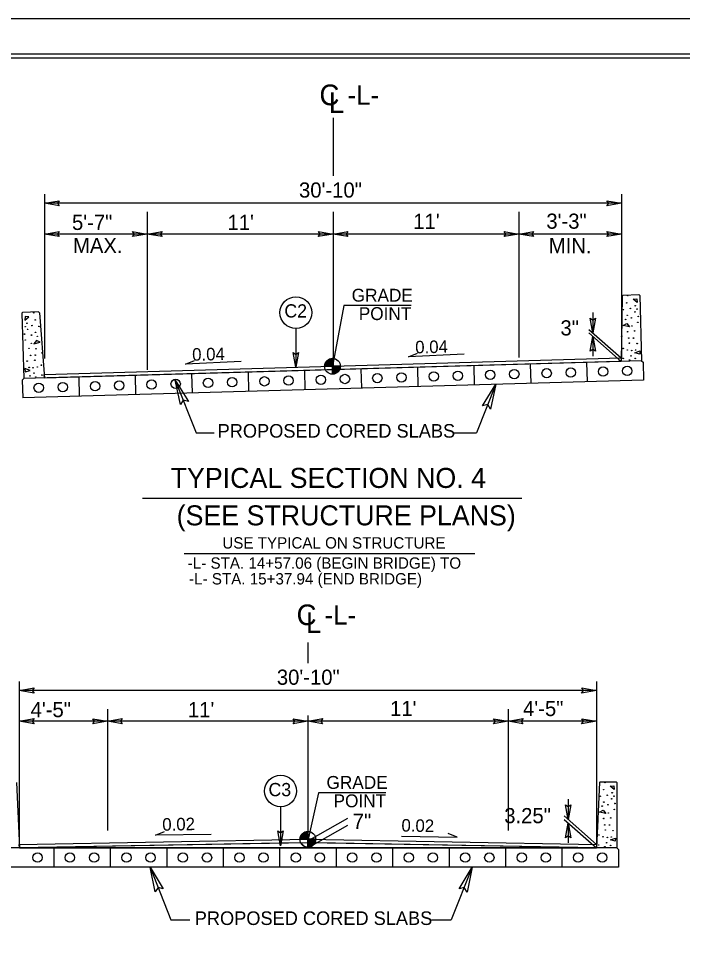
# Model space of a CAD drawing. Extents: x 573687 to 575553, y -54556 to -52223.
# Drawn here: x 574539 to 574960, y -52818 to -52223 of the extents above; entities that cross this region are included whole.
import ezdxf

# ---------------------------------------------------------------- set-up
doc = ezdxf.new("R2010")
doc.units = 0
for name, color, linetype in [('Old_Level_1', 7, 'Continuous'), ('Old_Level_11', 7, 'Continuous'), ('Old_Level_35', 7, 'Continuous'), ('Prop Dimension', 7, 'Continuous'), ('Prop Dimension Text', 7, 'Continuous'), ('Sheet Cutting Line CELL', 7, 'Continuous'), ('Sheet Plot Border Inside CELL', 7, 'Continuous'), ('Sheet Plot Border Outside CELL', 7, 'Continuous'), ('Sheet Typical CELL', 7, 'Continuous'), ('Typical Bridge Rail CELL', 7, 'Continuous'), ('Typical Terminator CELL', 7, 'Continuous'), ('Typical Text Centerline CELL', 7, 'Continuous'), ('Typical Text Grade Point CELL', 7, 'Continuous'), ('Typical Text Label CELL', 7, 'Continuous')]:
    doc.layers.add(name, color=color, linetype=linetype)

msp = doc.modelspace()

# ---------------------------------------------------------------- linework, layer by layer
at = {"layer": 'Old_Level_1'}
for p, q in [((574929.04, -52400.96), (574931.37, -52400.62)), ((574931.37, -52400.62), (574931.59, -52402.96)), ((574931.59, -52402.96), (574929.04, -52400.96)), ((574542.83, -52411.79), (574542.75, -52414.15)), ((574542.75, -52414.15), (574545.18, -52412)), ((574545.18, -52412), (574542.83, -52411.79)), ((574922.69, -52417.62), (574925.06, -52416.28)), ((574926.88, -52418.34), (574922.69, -52417.62)), ((574925.06, -52416.28), (574926.88, -52418.34)), ((574550.03, -52427.06), (574548.34, -52429.23)), ((574548.34, -52429.23), (574552.47, -52428.27)), ((574552.47, -52428.27), (574550.03, -52427.06)), ((574786.36, -52437.5), (574792.21, -52435.19)), ((574821.79, -52435.83), (574786.36, -52437.5)), ((574930.19, -52435.06), (574933.43, -52433.75)), ((574933.25, -52435.77), (574930.19, -52435.06)), ((574933.43, -52433.75), (574933.25, -52435.77)), ((574934.5, -52440.05), (574541.98, -52451.34)), ((574644.68, -52442.15), (574650.53, -52439.84)), ((574680.12, -52440.48), (574644.68, -52442.15)), ((574863.72, -52442.21), (574864.07, -52454.21)), ((574899.57, -52441.18), (574899.92, -52453.17)), ((574935.45, -52440.95), (574935.78, -52452.27)), ((574542.68, -52444.99), (574542.98, -52446.99)), ((574545.99, -52446.11), (574542.68, -52444.99)), ((574542.98, -52446.99), (574545.99, -52446.11)), ((574648.61, -52448.4), (574648.96, -52460.39)), ((574684.46, -52447.37), (574684.81, -52459.36)), ((574720.31, -52446.33), (574720.66, -52458.33)), ((574756.17, -52445.3), (574756.51, -52457.3)), ((574792.02, -52444.27), (574792.36, -52456.27)), ((574827.87, -52443.24), (574828.22, -52455.24)), ((574541.08, -52452.3), (574541.4, -52463.61)), ((574935.78, -52452.27), (574541.4, -52463.61)), ((574576.91, -52450.46), (574577.25, -52462.46)), ((574612.76, -52449.43), (574613.1, -52461.42)), ((574638.24, -52452.27), (574651.53, -52485.76)), ((574841.81, -52454.97), (574829.59, -52485.76)), ((574651.53, -52485.76), (574663, -52485.76)), ((574814.88, -52485.76), (574829.59, -52485.76)), ((574914.5, -52710.39), (574916.84, -52710.11)), ((574917, -52712.46), (574914.5, -52710.39)), ((574916.84, -52710.11), (574917, -52712.46)), ((574907.68, -52726.85), (574910.09, -52725.58)), ((574911.84, -52727.7), (574907.68, -52726.85)), ((574910.09, -52725.58), (574911.84, -52727.7)), ((574625.63, -52741.53), (574631.48, -52739.22)), ((574817.37, -52742.66), (574811.53, -52740.34)), ((574661.1, -52740.94), (574625.63, -52741.53)), ((574781.9, -52742.06), (574817.37, -52742.66)), ((574914.68, -52744.5), (574917.95, -52743.29)), ((574917.71, -52745.29), (574914.68, -52744.5)), ((574917.95, -52743.29), (574917.71, -52745.29)), ((574918.83, -52749.61), (574526.16, -52749.61)), ((574561.09, -52749.74), (574561.09, -52761.74)), ((574596.96, -52749.74), (574596.96, -52761.74)), ((574632.83, -52749.74), (574632.83, -52761.74)), ((574668.7, -52749.74), (574668.7, -52761.74)), ((574704.56, -52749.74), (574704.56, -52761.74)), ((574740.43, -52749.74), (574740.43, -52761.74)), ((574776.3, -52749.74), (574776.3, -52761.74)), ((574812.16, -52749.74), (574812.16, -52761.74)), ((574848.03, -52749.74), (574848.03, -52761.74)), ((574883.9, -52749.74), (574883.9, -52761.74)), ((574919.76, -52750.54), (574919.76, -52761.86)), ((574919.76, -52761.86), (574525.23, -52761.86)), ((574622.23, -52761.86), (574635.52, -52795.36)), ((574826.87, -52761.86), (574813.58, -52795.36)), ((574635.52, -52795.36), (574647.44, -52795.36)), ((574801.05, -52795.36), (574813.58, -52795.36))]:
    msp.add_line(p, q, dxfattribs=at)
for centre, radius in [((574925.7, -52398.66), 0.174), ((574925.01, -52403.21), 0.174), ((574927.34, -52406.73), 0.174), ((574930.42, -52405.06), 0.174), ((574548.38, -52409.51), 0.174), ((574922.93, -52407.5), 0.174), ((574925.32, -52411.14), 0.174), ((574927.97, -52412.76), 0.174), ((574930.24, -52408.93), 0.174), ((574931.62, -52407.18), 0.174), ((574932.36, -52411.84), 0.174), ((574542.96, -52418.35), 0.174), ((574544.04, -52416.18), 0.174), ((574547.21, -52417.66), 0.174), ((574549.33, -52414.02), 0.174), ((574551.66, -52418.18), 0.174), ((574924.32, -52413.72), 0.174), ((574928.33, -52417.95), 0.174), ((574932.09, -52415.6), 0.174), ((574542.49, -52423.05), 0.174), ((574544.44, -52420.02), 0.174), ((574546.93, -52423.72), 0.174), ((574549.48, -52421.95), 0.174), ((574550.63, -52424.47), 0.174), ((574921.85, -52424.43), 0.174), ((574925.57, -52421.58), 0.174), ((574930, -52421.03), 0.174), ((574542.97, -52426.79), 0.174), ((574546.86, -52428.93), 0.174), ((574926.32, -52425.62), 0.174), ((574926.75, -52428.82), 0.174), ((574929.31, -52425.58), 0.174), ((574931.64, -52429.1), 0.174), ((574545.38, -52432.09), 0.174), ((574546.33, -52436.6), 0.174), ((574549.31, -52436.46), 0.174), ((574549.83, -52432.39), 0.174), ((574553.7, -52435.01), 0.174), ((574922.77, -52432.16), 0.174), ((574925.42, -52433.16), 0.174), ((574928.19, -52433.52), 0.174), ((574930.63, -52433.14), 0.174), ((574544.2, -52440.24), 0.174), ((574549.06, -52439.68), 0.174), ((574553.23, -52442.79), 0.174), ((574922.81, -52438.51), 0.174), ((574926.77, -52439.51), 0.174), ((574927.77, -52436.92), 0.174), ((574930.42, -52438.54), 0.174), ((574545.44, -52444.22), 0.174), ((574547.89, -52444.46), 0.174), ((574548.51, -52447.83), 0.174), ((574550.64, -52443.94), 0.174), ((574766.61, -52451.01), 2.98), ((574781.92, -52450.57), 2.98), ((574802.47, -52449.97), 2.98), ((574817.77, -52449.53), 2.98), ((574838.32, -52448.94), 2.98), ((574853.62, -52448.5), 2.98), ((574874.17, -52447.91), 2.98), ((574889.47, -52447.47), 2.98), ((574910.02, -52446.88), 2.98), ((574925.32, -52446.44), 2.98), ((574545.96, -52449.6), 0.174), ((574551.5, -52457.19), 2.98), ((574549.66, -52450.35), 0.174), ((574553.55, -52449.13), 0.174), ((574566.8, -52456.75), 2.98), ((574587.35, -52456.16), 2.98), ((574602.66, -52455.72), 2.98), ((574623.21, -52455.13), 2.98), ((574638.51, -52454.69), 2.98), ((574659.06, -52454.1), 2.98), ((574674.36, -52453.66), 2.98), ((574694.91, -52453.07), 2.98), ((574710.21, -52452.63), 2.98), ((574730.76, -52452.04), 2.98), ((574746.06, -52451.6), 2.98), ((574911.23, -52707.99), 0.174), ((574908.21, -52716.74), 0.174), ((574910.41, -52712.52), 0.174), ((574912.64, -52716.1), 0.174), ((574915.77, -52714.52), 0.174), ((574916.91, -52716.67), 0.174), ((574910.49, -52720.45), 0.174), ((574913.09, -52722.14), 0.174), ((574915.48, -52718.38), 0.174), ((574917.51, -52721.35), 0.174), ((574909.42, -52723.01), 0.174), ((574913.31, -52727.35), 0.174), ((574917.14, -52725.1), 0.174), ((574906.64, -52733.63), 0.174), ((574910.44, -52730.89), 0.174), ((574914.88, -52730.47), 0.174), ((574911.08, -52734.95), 0.174), ((574911.42, -52738.16), 0.174), ((574914.07, -52735), 0.174), ((574916.29, -52738.58), 0.174), ((574907.34, -52741.39), 0.174), ((574909.96, -52742.46), 0.174), ((574912.21, -52746.29), 0.174), ((574912.72, -52742.9), 0.174), ((574915.17, -52742.6), 0.174), ((574907.2, -52747.74), 0.174), ((574911.13, -52748.85), 0.174), ((574914.8, -52747.99), 0.174), ((574550.82, -52755.74), 2.98), ((574571.37, -52755.74), 2.98), ((574586.68, -52755.74), 2.98), ((574607.24, -52755.74), 2.98), ((574622.55, -52755.74), 2.98), ((574643.11, -52755.74), 2.98), ((574658.42, -52755.74), 2.98), ((574678.97, -52755.74), 2.98), ((574694.28, -52755.74), 2.98), ((574714.84, -52755.74), 2.98), ((574730.15, -52755.74), 2.98), ((574750.71, -52755.74), 2.98), ((574766.02, -52755.74), 2.98), ((574786.57, -52755.74), 2.98), ((574801.88, -52755.74), 2.98), ((574822.44, -52755.74), 2.98), ((574837.75, -52755.74), 2.98), ((574858.31, -52755.74), 2.98), ((574873.62, -52755.74), 2.98), ((574894.17, -52755.74), 2.98), ((574909.48, -52755.74), 2.98)]:
    msp.add_circle(centre, radius, dxfattribs=at)
at = {"layer": 'Old_Level_11'}
for points in [[(574641.53, -52467.9), (574638.24, -52452.27), (574646.68, -52465.95), (574643.34, -52465.11)], [(574833.48, -52468.6), (574841.81, -52454.97), (574838.57, -52470.72), (574836.71, -52467.82)], [(574625.52, -52777.5), (574622.23, -52761.86), (574630.67, -52775.55), (574627.33, -52774.71)], [(574818.54, -52775.5), (574826.87, -52761.86), (574823.63, -52777.61), (574821.77, -52774.71)]]:
    msp.add_lwpolyline(points, close=True, dxfattribs=at)
at = {"layer": 'Old_Level_35'}
for p, q in [((574734.5, -52443.51), (574733.29, -52442.3)), ((574735.19, -52443.51), (574733.44, -52441.76)), ((574735.91, -52443.51), (574733.67, -52441.27)), ((574736.63, -52443.51), (574733.92, -52440.82)), ((574737.34, -52443.51), (574734.23, -52440.39)), ((574738.04, -52443.51), (574734.54, -52440.01)), ((574738.18, -52442.92), (574734.93, -52439.67)), ((574738.18, -52442.21), (574735.3, -52439.36)), ((574738.18, -52441.49), (574735.75, -52439.09)), ((574738.18, -52440.77), (574736.24, -52438.84)), ((574738.18, -52440.08), (574736.78, -52438.66)), ((574738.18, -52439.36), (574737.34, -52438.53)), ((574738.18, -52438.64), (574737.99, -52438.49)), ((574738.18, -52443.51), (574738.18, -52438.47)), ((574738.18, -52443.51), (574733.13, -52443.51)), ((574733.78, -52443.51), (574733.17, -52442.9)), ((574738.18, -52448.55), (574738.18, -52443.51)), ((574743.19, -52443.51), (574738.18, -52443.51)), ((574738.18, -52443.62), (574741.67, -52447.14)), ((574738.18, -52444.34), (574741.29, -52447.45)), ((574738.18, -52445.05), (574740.87, -52447.74)), ((574738.18, -52445.77), (574740.42, -52448.01)), ((574738.18, -52446.49), (574739.92, -52448.24)), ((574738.18, -52447.18), (574739.38, -52448.39)), ((574738.18, -52447.9), (574738.78, -52448.5)), ((574738.76, -52443.51), (574742.01, -52446.76)), ((574739.47, -52443.51), (574742.32, -52446.35)), ((574740.19, -52443.51), (574742.59, -52445.93)), ((574740.89, -52443.51), (574742.83, -52445.44)), ((574741.6, -52443.51), (574743.02, -52444.9)), ((574742.32, -52443.51), (574743.13, -52444.34)), ((574743.04, -52443.51), (574743.19, -52443.66)), ((574722.5, -52743.49), (574719.25, -52740.24)), ((574722.5, -52742.78), (574719.63, -52739.93)), ((574722.5, -52742.06), (574720.08, -52739.66)), ((574722.5, -52741.34), (574720.57, -52739.41)), ((574722.5, -52740.65), (574721.11, -52739.23)), ((574722.5, -52739.93), (574721.67, -52739.1)), ((574722.5, -52739.21), (574722.32, -52739.06)), ((574722.5, -52744.08), (574722.5, -52739.04)), ((574722.5, -52744.08), (574717.46, -52744.08)), ((574718.1, -52744.08), (574717.5, -52743.47)), ((574718.82, -52744.08), (574717.61, -52742.87)), ((574719.52, -52744.08), (574717.77, -52742.33)), ((574720.23, -52744.08), (574717.99, -52741.84)), ((574720.95, -52744.08), (574718.24, -52741.39)), ((574721.67, -52744.08), (574718.55, -52740.96)), ((574722.36, -52744.08), (574718.87, -52740.58)), ((574722.5, -52749.12), (574722.5, -52744.08)), ((574727.51, -52744.08), (574722.5, -52744.08)), ((574722.5, -52744.19), (574726, -52747.71)), ((574722.5, -52744.91), (574725.61, -52748.02)), ((574722.5, -52745.62), (574725.19, -52748.31)), ((574722.5, -52746.34), (574724.74, -52748.58)), ((574723.08, -52744.08), (574726.33, -52747.33)), ((574723.8, -52744.08), (574726.65, -52746.92)), ((574724.52, -52744.08), (574726.91, -52746.5)), ((574725.21, -52744.08), (574727.16, -52746.01)), ((574725.93, -52744.08), (574727.34, -52745.47)), ((574726.65, -52744.08), (574727.45, -52744.91)), ((574727.36, -52744.08), (574727.52, -52744.23)), ((574722.5, -52747.06), (574724.24, -52748.81)), ((574722.5, -52747.75), (574723.7, -52748.96)), ((574722.5, -52748.47), (574723.1, -52749.07))]:
    msp.add_line(p, q, dxfattribs=at)
for centre in [(574738.17, -52443.51), (574722.49, -52744.08)]:
    msp.add_circle(centre, 5.03, dxfattribs=at)
at = {"layer": 'Prop Dimension'}
for p, q in [((574738.51, -52285.65), (574738.51, -52322.52)), ((574620.51, -52345.26), (574620.51, -52445.69)), ((574738.51, -52345.26), (574738.51, -52445.69)), ((574856.51, -52345.26), (574856.51, -52437.96)), ((574722.5, -52619.12), (574722.5, -52632.11)), ((574722.5, -52665.32), (574722.5, -52745)), ((574718, -52746.35), (574705.41, -52746.58)), ((574728.22, -52746.37), (574726.13, -52747.55)), ((574905.72, -52749.61), (574728.22, -52746.37)), ((574704.86, -52746.59), (574539.27, -52749.61)), ((574539.27, -52749.61), (574722.5, -52749.61)), ((574722.5, -52749.61), (574723.6, -52748.99)), ((574723.6, -52748.99), (574722.5, -52749.61)), ((574722.5, -52749.61), (574905.72, -52749.61)), ((574724.74, -52748.58), (574724.74, -52748.58))]:
    msp.add_line(p, q, dxfattribs=at)
for points in [[(574555.09, -52450.96), (574554.92, -52448.78), (574738.18, -52443.51), (574921.42, -52438.22), (574921.39, -52440.43), (574738.24, -52445.7)], [(574539.27, -52749.61), (574539.17, -52747.43), (574722.5, -52744.08), (574905.82, -52747.41), (574905.72, -52749.61), (574722.5, -52746.27)]]:
    msp.add_lwpolyline(points, close=True, dxfattribs=at)
for points in [[(574705.41, -52746.58), (574705.14, -52748.15), (574704.86, -52746.59)], [(574724.74, -52748.58), (574724.74, -52748.58)]]:
    msp.add_lwpolyline(points, dxfattribs=at)
for start, end in [(206.82742, 282.73905), (282.73905, 296.51574), (296.52436, 316.33788)]:
    msp.add_arc((574722.49, -52744.08), 5.03, start, end, dxfattribs=at)
at = {"layer": 'Prop Dimension Text'}
for p, q in [((574555.21, -52334.17), (574555.21, -52438.48)), ((574921.8, -52334.17), (574921.8, -52438.48)), ((574921.8, -52339.96), (574555.21, -52339.96)), ((574620.51, -52359.46), (574555.21, -52359.46)), ((574738.51, -52359.46), (574620.51, -52359.46)), ((574856.51, -52359.46), (574738.51, -52359.46)), ((574921.8, -52359.46), (574856.51, -52359.46)), ((574903.52, -52409.31), (574903.52, -52422.34)), ((574714.87, -52419.54), (574714.87, -52444.17)), ((574900.9, -52422.27), (574921.39, -52440.43)), ((574900.94, -52420.06), (574921.42, -52438.22)), ((574903.52, -52424.59), (574903.52, -52437.15)), ((574617.36, -52527.23), (574858.3, -52527.23)), ((574643.99, -52562.41), (574828.48, -52562.41)), ((574539.2, -52643.77), (574539.2, -52748.07)), ((574905.79, -52643.77), (574905.79, -52748.07)), ((574905.79, -52649.55), (574539.2, -52649.55)), ((574595.21, -52661.4), (574595.21, -52738.44)), ((574849.78, -52661.4), (574849.78, -52738.44)), ((574905.79, -52669.05), (574539.2, -52669.05)), ((574887.85, -52718.49), (574887.85, -52731.53)), ((574705.14, -52723.51), (574705.14, -52748.15)), ((574722.5, -52745), (574747.97, -52730.57)), ((574885.24, -52731.45), (574905.72, -52749.61)), ((574885.27, -52729.24), (574905.76, -52747.41)), ((574887.85, -52733.77), (574887.85, -52746.33)), ((574722.5, -52749.61), (574747.97, -52735.18))]:
    msp.add_line(p, q, dxfattribs=at)
for centre in [(574714.87, -52409.44), (574705.14, -52713.41)]:
    msp.add_circle(centre, 10.1, dxfattribs=at)
at = {"layer": 'Sheet Cutting Line CELL'}
msp.add_line((575371.43, -52222.67), (573687.43, -52222.67), dxfattribs=at)
at = {"layer": 'Sheet Plot Border Inside CELL'}
msp.add_lwpolyline([(575366.93, -52245.12), (573700.43, -52245.12), (573700.43, -53300.22), (575366.93, -53300.22)], close=True, dxfattribs=at)
at = {"layer": 'Sheet Plot Border Outside CELL'}
msp.add_lwpolyline([(575371.43, -52222.67), (573687.43, -52222.67), (573687.43, -53322.67), (575371.43, -53322.67)], close=True, dxfattribs=at)
at = {"layer": 'Sheet Typical CELL'}
msp.add_lwpolyline([(575354.43, -52247.67), (573854.43, -52247.67), (573854.43, -53297.67), (575354.43, -53297.67)], close=True, dxfattribs=at)
at = {"layer": 'Typical Bridge Rail CELL'}
for p, q in [((574922.14, -52398.86), (574921.39, -52440.43)), ((574922.14, -52398.86), (574922.71, -52398.26)), ((574922.71, -52398.26), (574932.76, -52397.97)), ((574932.76, -52397.97), (574933.3, -52398.48)), ((574933.3, -52398.48), (574934.5, -52440.05)), ((574541.29, -52409.23), (574540.78, -52409.77)), ((574540.78, -52409.77), (574541.98, -52451.34)), ((574551.34, -52408.95), (574541.29, -52409.23)), ((574551.94, -52409.51), (574551.34, -52408.95)), ((574551.94, -52409.51), (574555.09, -52450.96)), ((574934.5, -52440.05), (574935.45, -52440.95)), ((574541.98, -52451.34), (574541.08, -52452.3)), ((574537.32, -52708.09), (574539.27, -52749.61)), ((574907.67, -52708.09), (574905.72, -52749.61)), ((574907.67, -52708.09), (574908.25, -52707.51)), ((574908.25, -52707.51), (574918.31, -52707.51)), ((574918.31, -52707.51), (574918.83, -52708.03)), ((574918.83, -52708.03), (574918.83, -52749.61)), ((574918.83, -52749.61), (574919.76, -52750.54))]:
    msp.add_line(p, q, dxfattribs=at)
at = {"layer": 'Typical Terminator CELL'}
for points in [[(574564.56, -52341.57), (574555.21, -52339.96), (574564.61, -52338.29), (574563.42, -52339.96)], [(574912.46, -52338.35), (574921.8, -52339.96), (574912.4, -52341.62), (574913.6, -52339.96)], [(574564.56, -52361.07), (574555.21, -52359.46), (574564.61, -52357.8), (574563.42, -52359.46)], [(574611.16, -52357.85), (574620.51, -52359.46), (574611.11, -52361.12), (574612.3, -52359.46)], [(574629.86, -52361.07), (574620.51, -52359.46), (574629.91, -52357.8), (574628.71, -52359.46)], [(574729.16, -52357.85), (574738.51, -52359.46), (574729.11, -52361.12), (574730.3, -52359.46)], [(574747.86, -52361.07), (574738.51, -52359.46), (574747.91, -52357.8), (574746.71, -52359.46)], [(574847.16, -52357.85), (574856.51, -52359.46), (574847.11, -52361.12), (574848.3, -52359.46)], [(574865.86, -52361.07), (574856.51, -52359.46), (574865.91, -52357.8), (574864.71, -52359.46)], [(574912.46, -52357.85), (574921.8, -52359.46), (574912.4, -52361.12), (574913.6, -52359.46)], [(574905.15, -52413), (574903.52, -52422.34), (574901.88, -52412.94), (574903.54, -52414.14)], [(574901.87, -52433.93), (574903.52, -52424.59), (574905.14, -52433.99), (574903.48, -52432.79)], [(574716.48, -52434.82), (574714.87, -52444.17), (574713.2, -52434.77), (574714.87, -52435.97)], [(574548.55, -52651.16), (574539.2, -52649.55), (574548.6, -52647.89), (574547.41, -52649.55)], [(574896.44, -52647.94), (574905.79, -52649.55), (574896.39, -52651.21), (574897.59, -52649.55)], [(574548.55, -52670.66), (574539.2, -52669.05), (574548.6, -52667.39), (574547.41, -52669.05)], [(574585.86, -52667.44), (574595.21, -52669.05), (574585.8, -52670.72), (574587, -52669.05)], [(574604.55, -52670.66), (574595.21, -52669.05), (574604.61, -52667.39), (574603.41, -52669.05)], [(574713.15, -52667.44), (574722.5, -52669.05), (574713.09, -52670.72), (574714.29, -52669.05)], [(574731.84, -52670.66), (574722.5, -52669.05), (574731.9, -52667.39), (574730.7, -52669.05)], [(574840.44, -52667.44), (574849.78, -52669.05), (574840.38, -52670.72), (574841.58, -52669.05)], [(574859.13, -52670.66), (574849.78, -52669.05), (574859.19, -52667.39), (574857.99, -52669.05)], [(574896.44, -52667.44), (574905.79, -52669.05), (574896.39, -52670.72), (574897.59, -52669.05)], [(574889.49, -52722.19), (574887.85, -52731.53), (574886.21, -52722.13), (574887.87, -52723.32)], [(574886.2, -52743.11), (574887.85, -52733.77), (574889.47, -52743.18), (574887.82, -52741.98)], [(574706.75, -52738.8), (574705.14, -52748.15), (574703.47, -52738.75), (574705.14, -52739.94)]]:
    msp.add_lwpolyline(points, close=True, dxfattribs=at)
at = {"layer": 'Typical Text Grade Point CELL'}
for points in [[(574788.08, -52404.87), (574745.26, -52404.87), (574738.18, -52443.51)], [(574772.07, -52714.47), (574729.25, -52714.47), (574722.5, -52745)]]:
    msp.add_lwpolyline(points, dxfattribs=at)

# ---------------------------------------------------------------- texts
at = {"layer": 'Old_Level_1'}
for p in [(574665.17, -52488.86), (574650.63, -52798.54)]:
    msp.add_text('PROPOSED CORED SLABS', height=8.64, rotation=0.00009, dxfattribs=at).set_placement(p)
at = {"layer": 'Prop Dimension Text'}
for s, height, p in [('30\'-10"', 9.623, (574716.86, -52336.31)), ('5\'-7"', 9.623, (574572.67, -52356.89)), (" 11'", 9.623, (574667.86, -52356.89)), (" 11'", 9.623, (574785.86, -52356.18)), ('3\'-3"', 9.623, (574873.97, -52356.1)), ('MAX.', 9.623, (574573.3, -52371.58)), ('MIN.', 9.623, (574875.51, -52371.69)), ('C2', 8.415, (574707.57, -52412.52)), (' 3"', 9.623, (574879.34, -52423.91)), ('30\'-10"', 9.623, (574702.78, -52645.9)), (' 4\'-5"', 9.623, (574542.78, -52666.49)), (" 11'", 9.623, (574642.71, -52666.49)), (" 11'", 9.623, (574771.11, -52665.78)), (' 4\'-5"', 9.623, (574855.61, -52665.78)), ('C3', 8.415, (574697.47, -52716.71)), (' 3.25"', 9.623, (574843.65, -52733.85))]:
    msp.add_text(s, height=height, rotation=0.00009, dxfattribs=at).set_placement(p)
msp.add_text('7"', height=9.623, dxfattribs=at).set_placement((574751, -52737.44))
at = {"layer": 'Typical Text Centerline CELL'}
for s, height, rotation, p in [('C', 13.15, 0.00011, (574729.84, -52277.63)), ('L', 13.15, 0.00011, (574735.8, -52282.57)), ('-L-', 12.329, 0.00009, (574747.62, -52277.28)), ('C', 13.15, 0.00011, (574715.31, -52608.03)), ('-L-', 12.329, 0.00009, (574733.1, -52607.68)), ('L', 13.15, 0.00011, (574721.28, -52612.97))]:
    msp.add_text(s, height=height, rotation=rotation, dxfattribs=at).set_placement(p)
at = {"layer": 'Typical Text Grade Point CELL'}
for s, p in [('GRADE ', (574750.31, -52402.45)), ('POINT', (574754.81, -52414.13)), ('GRADE ', (574734.3, -52712.05)), ('POINT', (574738.8, -52723.73))]:
    msp.add_text(s, height=8.179, rotation=0.00011, dxfattribs=at).set_placement(p)
at = {"layer": 'Typical Text Label CELL'}
for s, height, rotation, p in [(' 0.04', 7.978, 1.19186, (574787.79, -52435.41)), (' 0.04', 7.978, 1.19186, (574646.11, -52440.06)), ('TYPICAL SECTION NO. 4', 12.7159, 0.00011, (574635.31, -52520.81)), ('(SEE STRUCTURE PLANS)', 12.7159, 0.00011, (574639.14, -52544.61)), ('USE TYPICAL ON STRUCTURE', 7.2, 359.99997, (574668.17, -52559.33)), ('-L- STA. 14+57.06 (BEGIN BRIDGE) TO', 7.2, 359.99997, (574646.2, -52572.15)), ('-L- STA. 15+37.94 (END BRIDGE)', 7.2, 359.99997, (574647.04, -52582.16)), (' 0.02', 7.978, 1.19186, (574627.13, -52738.74)), (' 0.02', 7.978, 358.80833, (574778.9, -52739.07))]:
    msp.add_text(s, height=height, rotation=rotation, dxfattribs=at).set_placement(p)

doc.saveas('drawing.dxf')
